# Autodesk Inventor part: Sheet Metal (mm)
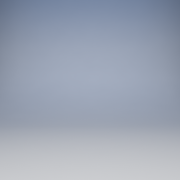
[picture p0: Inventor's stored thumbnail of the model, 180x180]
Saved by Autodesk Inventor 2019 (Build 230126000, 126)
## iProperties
Created: 2018-02
Part Number: Sheet Metal (mm)
Material: Všeobecné
Document SubType Name: Plech
Density: 1 g/cm^3
Sheet Metal Rule: Výchozí_mm
Appearance: Výchozí
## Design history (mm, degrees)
other parameters: "Tloušťka" = 0.5 (derived), "KSoučinitel" = 4.4, "PoloměrOhybu" = 0.5 (= Tloušťka), "ŠířkaVýštipu" = 0.5 (= Tloušťka), "HloubkaVýštipu" = 0.25 (= 0.5 x Tloušťka), "VelikostRohovéhoVýštipu" = 2 (= 4 x Tloušťka), "MezeraVystřižení" = 0.01, "MinimálníZbytek" = 1 (= 2 x Tloušťka), "PřechodovýPoloměr" = 0.5 (= PoloměrOhybu), "VelikostJacobihoPoloměru" = 0.5 (= PoloměrOhybu), "VelikostMezery" = 0.5 (= Tloušťka)
